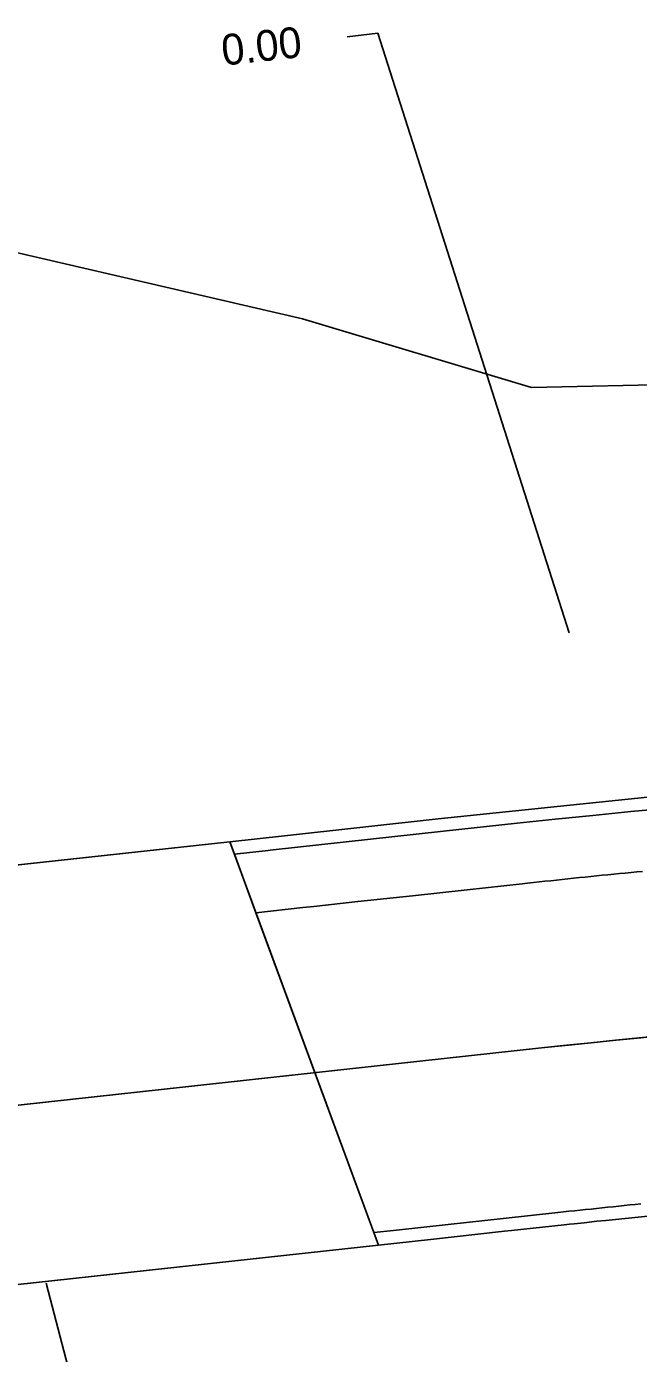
# Model space of a CAD drawing. Extents: x 1509538 to 1510847, y 401283 to 402022.
# Drawn here: x 1510046.4 to 1510102, y 401673.7 to 401794 of the extents above; entities that cross this region are included whole.
import ezdxf

# ---------------------------------------------------------------- set-up
doc = ezdxf.new("R2010")
doc.units = 0
for name, color, linetype in [('LDEFAULT_P', 7, 'Continuous'), ('Level 14', 7, 'Continuous'), ('Level 16', 7, 'Continuous'), ('Level 24', 7, 'Continuous'), ('Level 3', 7, 'Continuous'), ('RDEFAULT', 7, 'Continuous')]:
    doc.layers.add(name, color=color, linetype=linetype)

msp = doc.modelspace()

# ---------------------------------------------------------------- linework, layer by layer
at = {"layer": 'LDEFAULT_P'}
msp.add_lwpolyline([(1510048.22, 401680.04), (1510053.95, 401658.05), (1510094.78, 401662.5)], dxfattribs=at)
at = {"layer": 'Level 14'}
for p, q in [((1510068.53, 401719.32), (1510084.26, 401721.04)), ((1510084.26, 401721.04), (1510090.95, 401721.77)), ((1509978.25, 401710.66), (1510064.87, 401720.1)), ((1510064.87, 401720.1), (1510065.29, 401718.97)), ((1510065.29, 401718.97), (1510068.36, 401719.31)), ((1510065.29, 401718.97), (1510065.29, 401718.97)), ((1510068.36, 401719.31), (1510068.53, 401719.32)), ((1510093.17, 401701.39), (1509995.51, 401690.74))]:
    msp.add_line(p, q, dxfattribs=at)
for radius in [820.5, 800]:
    msp.add_arc((1510179.87, 400906.1), radius, 80.78048, 96.2219, dxfattribs=at)
at = {"layer": 'Level 16'}
for p, q in [((1509995.51, 401690.74), (1510093.17, 401701.39)), ((1510094.64, 401686.46), (1510089.67, 401685.92)), ((1510095.14, 401686.52), (1510094.64, 401686.46)), ((1510095.64, 401686.57), (1510095.14, 401686.52)), ((1510096.15, 401686.62), (1510095.64, 401686.57)), ((1510096.65, 401686.68), (1510096.15, 401686.62)), ((1510097.15, 401686.73), (1510096.65, 401686.68)), ((1510097.65, 401686.78), (1510097.15, 401686.73)), ((1510098.15, 401686.84), (1510097.65, 401686.78)), ((1510098.65, 401686.89), (1510098.15, 401686.84)), ((1510099.15, 401686.94), (1510098.65, 401686.89)), ((1510099.66, 401686.99), (1510099.15, 401686.94)), ((1510100.16, 401687.04), (1510099.66, 401686.99)), ((1510100.66, 401687.09), (1510100.16, 401687.04)), ((1510101.16, 401687.15), (1510100.66, 401687.09)), ((1510101.66, 401687.19), (1510101.16, 401687.15)), ((1510102.16, 401687.25), (1510101.66, 401687.19)), ((1510084.7, 401685.38), (1510079.73, 401684.83)), ((1510089.67, 401685.92), (1510084.7, 401685.38)), ((1510079.73, 401684.83), (1510077.93, 401684.64)), ((1510077.93, 401684.64), (1510077.93, 401684.64)), ((1510077.93, 401684.64), (1510078.35, 401683.51)), ((1510078.35, 401683.51), (1510008.39, 401675.88))]:
    msp.add_line(p, q, dxfattribs=at)
msp.add_arc((1510179.87, 400906.1), 800, 85.84827, 96.2219, dxfattribs=at)
at = {"layer": 'Level 24'}
msp.add_lwpolyline([(1509965.11, 401725.82), (1510041.03, 401773.36), (1510042.45, 401774.24), (1510071.47, 401767.53), (1510092.26, 401761.29), (1510106.06, 401761.59), (1510116.39, 401753.93), (1510166.17, 401754.62), (1510168.79, 401755.02), (1510188.36, 401755.57), (1510240.81, 401744.39), (1510296.54, 401763.85), (1510359.87, 401749.85), (1510436.07, 401732.12)], dxfattribs=at)
at = {"layer": 'Level 3'}
for p, q in [((1510083.79, 401722.16), (1510069.82, 401720.64)), ((1510069.82, 401720.64), (1510064.87, 401720.1)), ((1510064.87, 401720.1), (1510065.29, 401718.97)), ((1510065.29, 401718.97), (1510067.24, 401713.65)), ((1510086.42, 401715.74), (1510091.39, 401716.28)), ((1510091.39, 401716.28), (1510091.9, 401716.34)), ((1510091.9, 401716.34), (1510092.42, 401716.4)), ((1510092.42, 401716.4), (1510092.95, 401716.45)), ((1510092.95, 401716.45), (1510093.47, 401716.51)), ((1510093.47, 401716.51), (1510093.99, 401716.56)), ((1510093.99, 401716.56), (1510094.51, 401716.62)), ((1510094.51, 401716.62), (1510095.03, 401716.67)), ((1510095.03, 401716.67), (1510095.55, 401716.73)), ((1510095.55, 401716.73), (1510096.07, 401716.78)), ((1510096.07, 401716.78), (1510096.59, 401716.84)), ((1510096.59, 401716.84), (1510097.11, 401716.89)), ((1510097.11, 401716.89), (1510097.63, 401716.94)), ((1510097.63, 401716.94), (1510098.15, 401716.99)), ((1510098.15, 401716.99), (1510098.67, 401717.05)), ((1510098.67, 401717.05), (1510099.19, 401717.1)), ((1510099.19, 401717.1), (1510099.71, 401717.15)), ((1510099.71, 401717.15), (1510100.24, 401717.2)), ((1510100.24, 401717.2), (1510100.76, 401717.25)), ((1510100.76, 401717.25), (1510101.28, 401717.3)), ((1510101.28, 401717.3), (1510101.8, 401717.35)), ((1510101.8, 401717.35), (1510102.32, 401717.4)), ((1510076.48, 401714.66), (1510081.45, 401715.2)), ((1510081.45, 401715.2), (1510086.42, 401715.74)), ((1510067.24, 401713.65), (1510071.5, 401714.12)), ((1510071.5, 401714.12), (1510072.5, 401714.22)), ((1510072.5, 401714.22), (1510076.48, 401714.66))]:
    msp.add_line(p, q, dxfattribs=at)
for points in [[(1510103.19, 401723.01), (1510102.77, 401724.14), (1510083.79, 401722.16)], [(1510102.79, 401686.13), (1510098.99, 401685.74), (1510098.18, 401685.67), (1510097.03, 401685.54), (1510096.13, 401685.44), (1510095.7, 401685.4), (1510095.2, 401685.34), (1510090.44, 401684.82), (1510089.79, 401684.76), (1510083.07, 401684.02), (1510078.35, 401683.51), (1510077.93, 401684.64), (1510067.24, 401713.65), (1510071.5, 401714.12), (1510072.5, 401714.22), (1510076.48, 401714.66), (1510081.45, 401715.2), (1510086.42, 401715.74), (1510091.39, 401716.28), (1510091.9, 401716.34), (1510092.42, 401716.4), (1510092.95, 401716.45), (1510093.47, 401716.51), (1510093.99, 401716.56), (1510094.51, 401716.62), (1510095.03, 401716.67), (1510095.55, 401716.73), (1510096.07, 401716.78), (1510096.59, 401716.84), (1510097.11, 401716.89), (1510097.63, 401716.94), (1510098.15, 401716.99), (1510098.67, 401717.05), (1510099.19, 401717.1), (1510099.71, 401717.15), (1510100.24, 401717.2), (1510100.76, 401717.25), (1510101.28, 401717.3), (1510101.8, 401717.35), (1510102.32, 401717.4)]]:
    msp.add_lwpolyline(points, dxfattribs=at)
msp.add_lwpolyline([(1509978.25, 401710.66), (1510064.87, 401720.1), (1510078.35, 401683.51), (1510010.94, 401676.16), (1510006.96, 401678.8), (1509984.13, 401703.87)], close=True, dxfattribs=at)
at = {"layer": 'RDEFAULT'}
msp.add_lwpolyline([(1510095.68, 401739.05), (1510078.3, 401793.43), (1510075.52, 401793.12)], dxfattribs=at)

# ---------------------------------------------------------------- texts
msp.add_text('0.00', height=2.8, rotation=6.2215, dxfattribs=at).set_placement((1510064.27, 401790.49))

doc.saveas('drawing.dxf')
